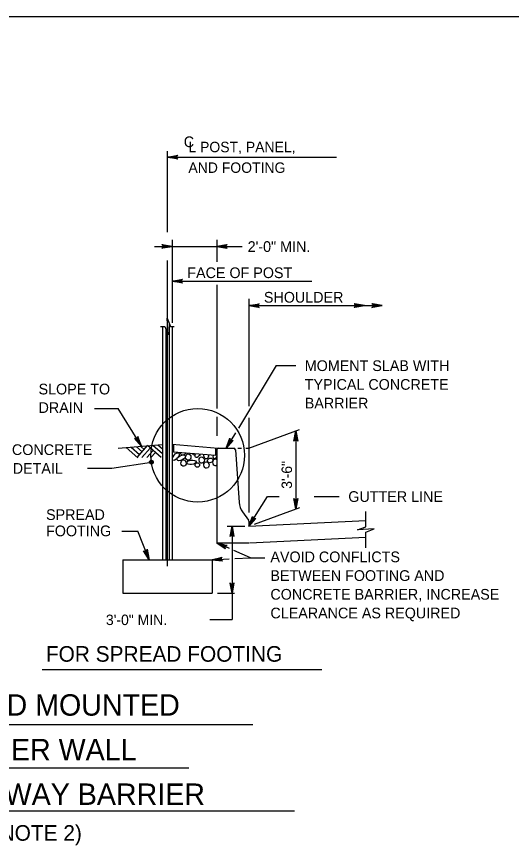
# Model space of a CAD drawing. Extents: x 3761 to 5458, y -616 to 1166.
# Drawn here: x 4800.4 to 4942.5, y 318.7 to 556.7 of the extents above; entities that cross this region are included whole.
import ezdxf

# ---------------------------------------------------------------- set-up
doc = ezdxf.new("R2010")
doc.units = 0
doc.layers.add('1', color=7, linetype='Continuous')
doc.layers.add('2', color=7, linetype='Continuous')

msp = doc.modelspace()

# ---------------------------------------------------------------- linework, layer by layer
at = {"layer": '1'}
for p, q in [((4843.7, 494.79), (4843.7, 518.08)), ((4843.7, 516.32), (4892.25, 516.32)), ((4839.98, 490.72), (4865.13, 490.72)), ((4845.08, 492.57), (4845.08, 468.78)), ((4857.88, 492.57), (4857.88, 486.29)), ((4843.7, 398.88), (4843.7, 486.64)), ((4845.08, 480.75), (4885.13, 480.75)), ((4857.88, 479.64), (4857.88, 444.19)), ((4867.08, 475.68), (4867.08, 444.8)), ((4867.08, 473.7), (4905.41, 473.7)), ((4841.68, 467.75), (4842.94, 467.75)), ((4842.32, 467.75), (4842.32, 400.76)), ((4843.21, 467.08), (4843.21, 400.76)), ((4844.18, 468.68), (4844.18, 400.76)), ((4844.54, 467.75), (4845.59, 467.75)), ((4845.08, 467.75), (4845.08, 400.76)), ((4874.91, 456.56), (4864.06, 438.55)), ((4874.91, 456.56), (4880.56, 456.56)), ((4822.77, 444.14), (4829.54, 444.14)), ((4836.28, 433.33), (4829.54, 444.14)), ((4857.88, 441.82), (4857.88, 436.36)), ((4867.08, 441.5), (4867.08, 414.34)), ((4867.08, 432.76), (4881.65, 438.13)), ((4863.24, 437.18), (4860.58, 432.76)), ((4880.56, 437.73), (4880.56, 415.33)), ((4829.52, 432.76), (4842.32, 433.83)), ((4834.82, 433.15), (4836.41, 431.73)), ((4835, 430.15), (4837.99, 433.51)), ((4836.15, 433.16), (4837.02, 432.39)), ((4841.86, 430.06), (4837.99, 433.51)), ((4842.27, 431.11), (4839.48, 433.59)), ((4842.27, 432.53), (4840.98, 433.68)), ((4858.24, 432.73), (4845.08, 433.83)), ((4845.48, 433.8), (4845.48, 431.66)), ((4831.83, 432.97), (4835.18, 429.98)), ((4833.32, 433.06), (4835.7, 430.94)), ((4836.33, 430.06), (4838.78, 432.8)), ((4837.75, 430.06), (4839.57, 432.09)), ((4838.95, 430.06), (4840.25, 431.51)), ((4857.48, 430.66), (4845.48, 431.66)), ((4857.48, 432.8), (4857.48, 430.66)), ((4857.88, 432.23), (4857.88, 405.56)), ((4858.41, 432.76), (4862.72, 432.76)), ((4863.25, 432.27), (4864.31, 417.2)), ((4863.93, 432.76), (4864.98, 432.76)), ((4866.21, 432.76), (4867.08, 432.76)), ((4827.7, 427.06), (4839.08, 428.76)), ((4820.78, 427.06), (4827.7, 427.06)), ((4867.08, 410.36), (4872.43, 418.94)), ((4872.43, 418.94), (4875.79, 418.94)), ((4885.85, 418.94), (4893.01, 418.94)), ((4865.29, 414.47), (4866.98, 412.1)), ((4868.67, 410.95), (4881.69, 415.74)), ((4900.69, 410.24), (4900.69, 414.59)), ((4867.08, 410.36), (4900.69, 411.99)), ((4867.08, 411.79), (4867.08, 410.36)), ((4860.85, 410.36), (4865.89, 410.36)), ((4862.24, 410.36), (4862.24, 383.64)), ((4830.64, 408.97), (4835.18, 408.97)), ((4838.44, 400.76), (4835.18, 408.97)), ((4867.31, 405.58), (4900.69, 407.19)), ((4900.69, 404.13), (4900.69, 408.64)), ((4857.88, 405.56), (4867.08, 405.56)), ((4830.9, 400.76), (4830.9, 391.16)), ((4830.9, 400.76), (4856.5, 400.76)), ((4856.5, 400.76), (4861.41, 401)), ((4856.5, 400.76), (4856.5, 391.16)), ((4863.04, 401.07), (4867.51, 401.29)), ((4867.51, 401.29), (4871.68, 401.29)), ((4830.9, 391.16), (4856.5, 391.16)), ((4858.09, 391.16), (4862.99, 391.16)), ((4855.92, 383.64), (4862.24, 383.64)), ((4807.76, 369.28), (4888.03, 369.28)), ((4722.53, 353.42), (4868.22, 353.42)), ((4741.09, 341.04), (4849.84, 341.04)), ((4711.22, 328.65), (4880.17, 328.65))]:
    msp.add_line(p, q, dxfattribs=at)
for points in [[(4843.7, 516.32), (4846.68, 516.88), (4846.45, 516.72), (4846.33, 516.52), (4846.3, 516.32), (4846.33, 516.12), (4846.45, 515.92), (4846.68, 515.76), (4843.7, 516.32), (4846.45, 515.92), (4846.33, 516.12), (4843.7, 516.32), (4846.3, 516.32), (4846.33, 516.52), (4843.7, 516.32), (4846.45, 516.72)], [(4845.08, 490.72), (4842.1, 490.16), (4842.21, 490.24), (4842.33, 490.32), (4842.39, 490.42), (4842.45, 490.52), (4842.46, 490.62), (4842.48, 490.72), (4842.46, 490.82), (4842.45, 490.92), (4842.39, 491.02), (4842.33, 491.12), (4842.21, 491.2), (4842.1, 491.28), (4845.08, 490.72), (4842.21, 491.2), (4842.33, 491.12), (4845.08, 490.72), (4842.39, 491.02), (4842.45, 490.92), (4845.08, 490.72), (4842.46, 490.82), (4842.48, 490.72), (4845.08, 490.72), (4842.46, 490.62), (4842.45, 490.52), (4845.08, 490.72), (4842.39, 490.42), (4842.33, 490.32), (4845.08, 490.72), (4842.21, 490.24)], [(4857.88, 490.72), (4860.86, 491.28), (4860.75, 491.2), (4860.63, 491.12), (4860.57, 491.02), (4860.51, 490.92), (4860.5, 490.82), (4860.48, 490.72), (4860.5, 490.62), (4860.51, 490.52), (4860.57, 490.42), (4860.63, 490.32), (4860.75, 490.24), (4860.86, 490.16), (4857.88, 490.72), (4860.75, 490.24), (4860.63, 490.32), (4857.88, 490.72), (4860.57, 490.42), (4860.51, 490.52), (4857.88, 490.72), (4860.5, 490.62), (4860.48, 490.72), (4857.88, 490.72), (4860.5, 490.82), (4860.51, 490.92), (4857.88, 490.72), (4860.57, 491.02), (4860.63, 491.12), (4857.88, 490.72), (4860.75, 491.2)], [(4845.08, 480.75), (4848.06, 481.31), (4847.83, 481.15), (4847.71, 480.95), (4847.68, 480.75), (4847.71, 480.55), (4847.83, 480.35), (4848.06, 480.19), (4845.08, 480.75), (4847.83, 480.35), (4847.71, 480.55), (4845.08, 480.75), (4847.68, 480.75), (4847.71, 480.95), (4845.08, 480.75), (4847.83, 481.15)], [(4867.08, 473.7), (4870.06, 474.26), (4869.83, 474.1), (4869.71, 473.9), (4869.68, 473.7), (4869.71, 473.5), (4869.83, 473.3), (4870.06, 473.14), (4867.08, 473.7), (4869.83, 473.3), (4869.71, 473.5), (4867.08, 473.7), (4869.68, 473.7), (4869.71, 473.9), (4867.08, 473.7), (4869.83, 474.1)], [(4900.29, 473.7), (4897.31, 473.14), (4897.42, 473.22), (4897.54, 473.3), (4897.6, 473.4), (4897.65, 473.5), (4897.67, 473.6), (4897.69, 473.7), (4897.67, 473.8), (4897.65, 473.9), (4897.6, 474), (4897.54, 474.1), (4897.42, 474.18), (4897.31, 474.26), (4900.29, 473.7), (4897.42, 474.18), (4897.54, 474.1), (4900.29, 473.7), (4897.6, 474), (4897.65, 473.9), (4900.29, 473.7), (4897.67, 473.8), (4897.69, 473.7), (4900.29, 473.7), (4897.67, 473.6), (4897.65, 473.5), (4900.29, 473.7), (4897.6, 473.4), (4897.54, 473.3), (4900.29, 473.7), (4897.42, 473.22)], [(4905.41, 473.7), (4902.43, 473.14), (4902.54, 473.22), (4902.66, 473.3), (4902.72, 473.4), (4902.77, 473.5), (4902.79, 473.6), (4902.81, 473.7), (4902.79, 473.8), (4902.77, 473.9), (4902.72, 474), (4902.66, 474.1), (4902.54, 474.18), (4902.43, 474.26), (4905.41, 473.7), (4902.54, 474.18), (4902.66, 474.1), (4905.41, 473.7), (4902.72, 474), (4902.77, 473.9), (4905.41, 473.7), (4902.79, 473.8), (4902.81, 473.7), (4905.41, 473.7), (4902.79, 473.6), (4902.77, 473.5), (4905.41, 473.7), (4902.72, 473.4), (4902.66, 473.3), (4905.41, 473.7), (4902.54, 473.22)], [(4842.94, 467.75), (4843.92, 465.35), (4843.62, 470.15), (4844.54, 467.75)], [(4836.28, 433.33), (4835.19, 436.16), (4835.18, 436.02), (4835.17, 435.88), (4835.12, 435.78), (4835.07, 435.67), (4834.99, 435.61), (4834.91, 435.54), (4834.82, 435.5), (4834.73, 435.46), (4834.61, 435.46), (4834.49, 435.46), (4834.37, 435.52), (4834.24, 435.57), (4836.28, 433.33), (4834.37, 435.52), (4834.49, 435.46), (4836.28, 433.33), (4834.61, 435.46), (4834.73, 435.46), (4836.28, 433.33), (4834.82, 435.5), (4834.91, 435.54), (4836.28, 433.33), (4834.99, 435.61), (4835.07, 435.67), (4836.28, 433.33), (4835.12, 435.78), (4835.17, 435.88), (4836.28, 433.33), (4835.18, 436.02)], [(4860.58, 432.76), (4861.64, 435.61), (4861.64, 435.47), (4861.65, 435.33), (4861.71, 435.23), (4861.76, 435.12), (4861.84, 435.06), (4861.92, 434.99), (4862.01, 434.96), (4862.11, 434.92), (4862.22, 434.92), (4862.34, 434.92), (4862.47, 434.97), (4862.59, 435.03), (4860.58, 432.76), (4862.47, 434.97), (4862.34, 434.92), (4860.58, 432.76), (4862.22, 434.92), (4862.11, 434.92), (4860.58, 432.76), (4862.01, 434.96), (4861.92, 434.99), (4860.58, 432.76), (4861.84, 435.06), (4861.76, 435.12), (4860.58, 432.76), (4861.71, 435.23), (4861.65, 435.33), (4860.58, 432.76), (4861.64, 435.47)], [(4880.56, 437.73), (4881.12, 434.75), (4881.04, 434.86), (4880.96, 434.98), (4880.86, 435.04), (4880.76, 435.09), (4880.66, 435.11), (4880.56, 435.13), (4880.46, 435.11), (4880.36, 435.09), (4880.26, 435.04), (4880.16, 434.98), (4880.08, 434.86), (4880, 434.75), (4880.56, 437.73), (4880.08, 434.86), (4880.16, 434.98), (4880.56, 437.73), (4880.26, 435.04), (4880.36, 435.09), (4880.56, 437.73), (4880.46, 435.11), (4880.56, 435.13), (4880.56, 437.73), (4880.66, 435.11), (4880.76, 435.09), (4880.56, 437.73), (4880.86, 435.04), (4880.96, 434.98), (4880.56, 437.73), (4881.04, 434.86)], [(4880.56, 415.33), (4880, 418.31), (4880.08, 418.2), (4880.16, 418.08), (4880.26, 418.02), (4880.36, 417.96), (4880.46, 417.95), (4880.56, 417.93), (4880.66, 417.95), (4880.76, 417.96), (4880.86, 418.02), (4880.96, 418.08), (4881.04, 418.2), (4881.12, 418.31), (4880.56, 415.33), (4881.04, 418.2), (4880.96, 418.08), (4880.56, 415.33), (4880.86, 418.02), (4880.76, 417.96), (4880.56, 415.33), (4880.66, 417.95), (4880.56, 417.93), (4880.56, 415.33), (4880.46, 417.95), (4880.36, 417.96), (4880.56, 415.33), (4880.26, 418.02), (4880.16, 418.08), (4880.56, 415.33), (4880.08, 418.2)], [(4867.08, 410.36), (4868.17, 413.2), (4868.18, 413.06), (4868.19, 412.92), (4868.24, 412.81), (4868.29, 412.71), (4868.37, 412.64), (4868.45, 412.58), (4868.54, 412.54), (4868.64, 412.5), (4868.75, 412.5), (4868.87, 412.5), (4869, 412.55), (4869.12, 412.61), (4867.08, 410.36), (4869, 412.55), (4868.87, 412.5), (4867.08, 410.36), (4868.75, 412.5), (4868.64, 412.5), (4867.08, 410.36), (4868.54, 412.54), (4868.45, 412.58), (4867.08, 410.36), (4868.37, 412.64), (4868.29, 412.71), (4867.08, 410.36), (4868.24, 412.81), (4868.19, 412.92), (4867.08, 410.36), (4868.18, 413.06)], [(4862.24, 410.36), (4862.8, 407.38), (4862.72, 407.5), (4862.64, 407.61), (4862.54, 407.67), (4862.44, 407.73), (4862.34, 407.75), (4862.24, 407.76), (4862.14, 407.75), (4862.04, 407.73), (4861.94, 407.67), (4861.84, 407.61), (4861.76, 407.5), (4861.68, 407.38), (4862.24, 410.36), (4861.76, 407.5), (4861.84, 407.61), (4862.24, 410.36), (4861.94, 407.67), (4862.04, 407.73), (4862.24, 410.36), (4862.14, 407.75), (4862.24, 407.76), (4862.24, 410.36), (4862.34, 407.75), (4862.44, 407.73), (4862.24, 410.36), (4862.54, 407.67), (4862.64, 407.61), (4862.24, 410.36), (4862.72, 407.5)], [(4900.69, 408.64), (4903.09, 409.62), (4898.29, 409.33), (4900.69, 410.24)], [(4857.88, 405.56), (4860.83, 404.86), (4860.7, 404.84), (4860.56, 404.81), (4860.46, 404.75), (4860.37, 404.68), (4860.31, 404.59), (4860.26, 404.51), (4860.23, 404.41), (4860.21, 404.31), (4860.22, 404.2), (4860.23, 404.08), (4860.31, 403.96), (4860.38, 403.84), (4857.88, 405.56), (4860.31, 403.96), (4860.23, 404.08), (4857.88, 405.56), (4860.22, 404.2), (4860.21, 404.31), (4857.88, 405.56), (4860.23, 404.41), (4860.26, 404.51), (4857.88, 405.56), (4860.31, 404.59), (4860.37, 404.68), (4857.88, 405.56), (4860.46, 404.75), (4860.56, 404.81), (4857.88, 405.56), (4860.7, 404.84)], [(4861.5, 403.96), (4857.88, 405.56)], [(4838.44, 400.76), (4836.82, 403.33), (4836.93, 403.25), (4837.05, 403.18), (4837.17, 403.16), (4837.28, 403.14), (4837.38, 403.16), (4837.48, 403.18), (4837.57, 403.23), (4837.65, 403.29), (4837.72, 403.38), (4837.79, 403.47), (4837.83, 403.61), (4837.86, 403.74), (4838.44, 400.76), (4837.83, 403.61), (4837.79, 403.47), (4838.44, 400.76), (4837.72, 403.38), (4837.65, 403.29), (4838.44, 400.76), (4837.57, 403.23), (4837.48, 403.18), (4838.44, 400.76), (4837.38, 403.16), (4837.28, 403.14), (4838.44, 400.76), (4837.17, 403.16), (4837.05, 403.18), (4838.44, 400.76), (4836.93, 403.25)], [(4867.51, 401.29), (4862.76, 403.4)], [(4856.5, 400.76), (4859.45, 401.46), (4859.34, 401.38), (4859.23, 401.29), (4859.17, 401.19), (4859.12, 401.09), (4859.11, 400.99), (4859.09, 400.89), (4859.12, 400.79), (4859.14, 400.69), (4859.2, 400.59), (4859.27, 400.5), (4859.38, 400.42), (4859.5, 400.35), (4856.5, 400.76), (4859.38, 400.42), (4859.27, 400.5), (4856.5, 400.76), (4859.2, 400.59), (4859.14, 400.69), (4856.5, 400.76), (4859.12, 400.79), (4859.09, 400.89), (4856.5, 400.76), (4859.11, 400.99), (4859.12, 401.09), (4856.5, 400.76), (4859.17, 401.19), (4859.23, 401.29), (4856.5, 400.76), (4859.34, 401.38)], [(4862.24, 391.16), (4861.68, 394.15), (4861.76, 394.03), (4861.84, 393.92), (4861.94, 393.86), (4862.04, 393.8), (4862.14, 393.78), (4862.24, 393.76), (4862.34, 393.78), (4862.44, 393.8), (4862.54, 393.86), (4862.64, 393.92), (4862.72, 394.03), (4862.8, 394.15), (4862.24, 391.16), (4862.72, 394.03), (4862.64, 393.92), (4862.24, 391.16), (4862.54, 393.86), (4862.44, 393.8), (4862.24, 391.16), (4862.34, 393.78), (4862.24, 393.76), (4862.24, 391.16), (4862.14, 393.78), (4862.04, 393.8), (4862.24, 391.16), (4861.94, 393.86), (4861.84, 393.92), (4862.24, 391.16), (4861.76, 394.03)]]:
    msp.add_lwpolyline(points, dxfattribs=at)
for centre, radius in [((4852.38, 430.74), 13.44), ((4839.08, 428.76), 0.533), ((4839.08, 428.76), 0.267)]:
    msp.add_circle(centre, radius, dxfattribs=at)
for centre, radius, start, end in [((4858.41, 432.23), 0.533, 90, 180), ((4862.72, 432.23), 0.533, 4.0219, 90), ((4869.63, 417.57), 5.33, 184.0219, 215.5414), ((4866.55, 411.79), 0.533, 0, 35.5414)]:
    msp.add_arc(centre, radius, start, end, dxfattribs=at)
for centre, major_axis, ratio in [((4846.1, 430.36), (-0.83, -1.05), 0.479042), ((4847.64, 430.02), (-1.19, -0.6), 0.479042), ((4849.69, 430.21), (-0.053, 0.902), 0.844245), ((4848.32, 428.49), (-0.053, 0.902), 0.844245), ((4850.58, 428.71), (-1.33, -0.16), 0.479042), ((4852.29, 427.95), (-0.451, 0.451), 0.982495), ((4853.54, 429.37), (-0.053, 0.902), 0.844245), ((4854.91, 427.93), (-0.053, 0.902), 0.844245), ((4855.97, 429.26), (0.767, 0.247), 0.796199)]:
    msp.add_ellipse(centre, major_axis=major_axis, ratio=ratio, dxfattribs=at)
for centre, major_axis, ratio, start_param, end_param in [((4848.27, 431.5), (0.788, 0.377), 0.646802, 2.514027, 5.440341), ((4851.24, 432.2), (0.16, -1.33), 0.479042, 5.504237, 6.86597), ((4852.55, 431.28), (-0.83, -1.05), 0.479042, 5.203222, 7.974892), ((4854.83, 430.68), (-0.053, 0.902), 0.844245, 1.226507, 4.816703), ((4857.33, 430.57), (0.279, 0.738), 0.687276, 1.636821, 4.886434), ((4857.43, 428.73), (-0.053, 0.902), 0.844245, 5.577625, 9.99132)]:
    msp.add_ellipse(centre, major_axis=major_axis, ratio=ratio, start_param=start_param, end_param=end_param, dxfattribs=at)
at = {"layer": '2'}
msp.add_line((4642.34, 556.69), (5428.34, 556.69), dxfattribs=at)

# ---------------------------------------------------------------- texts
at = {"layer": '1'}
for s, height, p in [('C', 3.07, (4848.39, 519.21)), ('L POST, PANEL,', 3, (4849.72, 517.75)), ('AND FOOTING', 3, (4849.72, 511.82)), ('2\'-0" MIN.', 3.072, (4866.74, 489.12)), ('FACE OF POST', 3.0721, (4849.41, 481.61)), ('SHOULDER', 3.072, (4871.41, 474.57)), ('MOMENT SLAB WITH', 3.0721, (4883.14, 454.93)), ('TYPICAL CONCRETE', 3.0721, (4883.14, 449.55)), ('SLOPE TO', 3.072, (4806.69, 448.21)), ('DRAIN', 3.072, (4806.69, 442.89)), ('BARRIER', 3.072, (4883.14, 444.18)), ('SEE CONCRETE', 3.0721, (4789.68, 430.82)), ('CAP DETAIL', 3.072, (4789.68, 425.44)), ('GUTTER LINE', 3.0721, (4895.64, 417.35)), ('SPREAD', 3.072, (4808.84, 412.17)), ('FOOTING', 3.072, (4808.84, 407.5)), ('AVOID CONFLICTS', 3.0721, (4873.27, 400.04)), ('BETWEEN FOOTING AND', 3.0721, (4873.27, 394.67)), ('CONCRETE BARRIER, INCREASE', 3.0721, (4873.27, 389.29)), ('CLEARANCE AS REQUIRED', 3.0721, (4873.27, 383.92)), ('3\'-0" MIN.', 3, (4826.04, 382)), ('FOR SPREAD FOOTING', 4.48, (4808.78, 371.47)), ('SECTION - GROUND MOUNTED', 6.1439, (4723.1, 355.99)), ('SOUND BARRIER WALL', 6.1439, (4741.7, 343.18)), ('ADJACENT TO ROADWAY BARRIER', 6.1439, (4713.88, 330.37)), ('OPTION 1 (SEE NOTE 2)', 4.48, (4750.22, 320.08))]:
    msp.add_text(s, height=height, dxfattribs=at).set_placement(p)
msp.add_text('3\'-6"', height=3, rotation=90, dxfattribs=at).set_placement((4879.47, 421.12))

doc.saveas('drawing.dxf')
